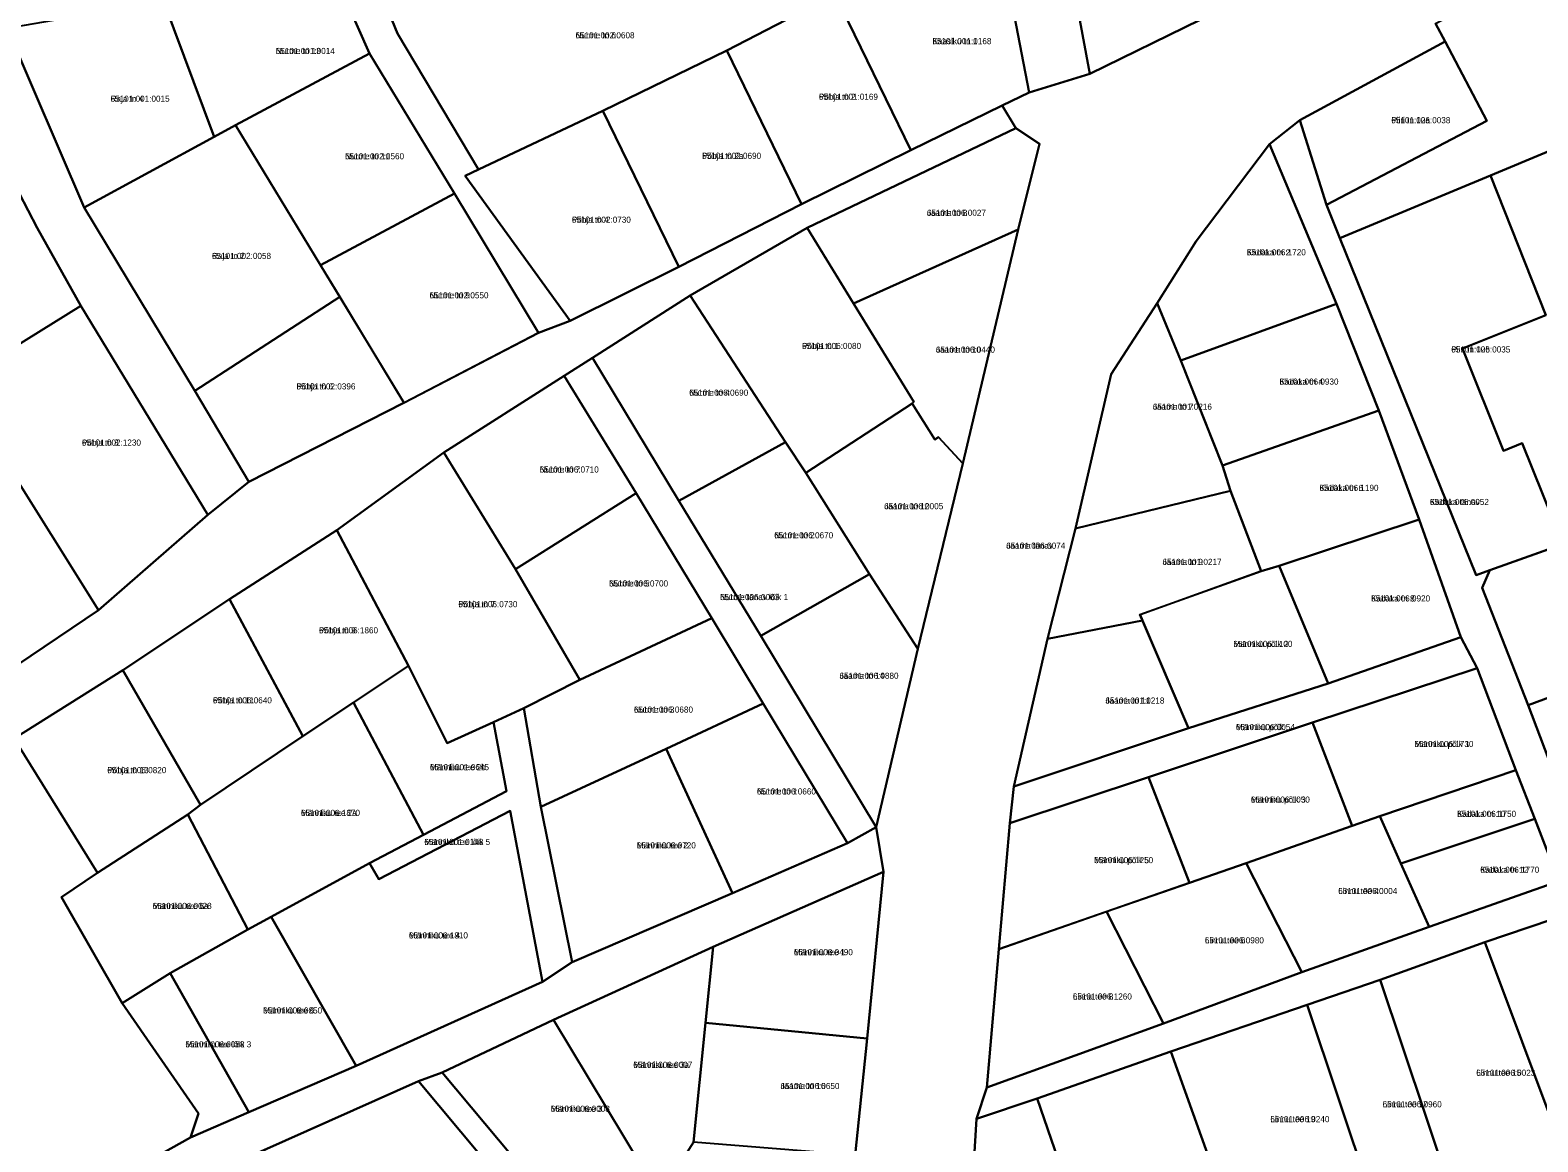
# Model space of a CAD drawing. Extents: x 556044 to 574504, y 6567077 to 6586269.
# Drawn here: x 560853.5 to 561223.9, y 6581367.4 to 6581640.5 of the extents above; entities that cross this region are included whole.
import ezdxf

# ---------------------------------------------------------------- set-up
doc = ezdxf.new("R2010")
doc.units = 0
for name, color, linetype in [('L_AADRESS', 7, 'Continuous'), ('PIIR', 7, 'Continuous'), ('TUNNUS', 7, 'Continuous')]:
    doc.layers.add(name, color=color, linetype=linetype)

msp = doc.modelspace()

# ---------------------------------------------------------------- linework, layer by layer
at = {"layer": 'PIIR'}
for points in [[(561073.04, 6582054.91), (561090.8, 6582052.25), (561063.5, 6581894.73), (561081.16, 6581800.3), (561086.75, 6581769.25), (561087.65, 6581765.33), (561095.83, 6581726.49), (561113.81, 6581629.73), (561098.93, 6581625.2), (561090.65, 6581668.07), (561080.32, 6581719.75), (561077.83, 6581733.6), (561073.27, 6581765.82), (561064.99, 6581804.94), (561063.2, 6581814.4), (561055.66, 6581860.95), (561050.77, 6581869.24), (561044.19, 6581869.12), (561046.86, 6581879.13), (561048.48, 6581913.41), (561048.56, 6581916.69), (561051.35, 6581917.01), (561064.29, 6581999.82)], [(560897.18, 6581521.41), (560865.96, 6581572.78), (560855.29, 6581591.94), (560850.86, 6581600.43), (560839.26, 6581625.44), (560835.81, 6581635.67), (560832.91, 6581651.09), (560829.15, 6581678.32), (560825.44, 6581705.91), (560821.71, 6581732.99), (560779.69, 6581727.72), (560778.17, 6581738.32), (560782.21, 6581739.06), (560790.39, 6581739.83), (560816.39, 6581742.34), (560828.68, 6581740.37), (560833.36, 6581733.14), (560834.71, 6581724.25), (560839.18, 6581696.6), (560843.5, 6581668.92), (560847.89, 6581640.98), (560866.8, 6581596.89), (560894, 6581551.88), (560907.3, 6581529.5)], [(561128.53, 6581730.52), (561140.95, 6581643.06), (561113.81, 6581629.73), (561095.83, 6581726.49)], [(560940.4, 6581647.93), (561002.17, 6581662.66), (561036.04, 6581670.75), (561041.6, 6581644.25), (561024.7, 6581635.46), (560994.21, 6581620.7), (560963.64, 6581606.24), (560943.81, 6581639.64)], [(561069.9, 6581611.01), (561051.43, 6581648.89), (561090.65, 6581668.07), (561098.93, 6581625.2), (561092.32, 6581621.96)], [(560898.72, 6581614.26), (560886.28, 6581647.65), (560928, 6581655.01), (560936.9, 6581634.78), (560904, 6581617.15)], [(561171.98, 6581597.55), (561211.35, 6581618.25), (561201.11, 6581637.72), (561198.78, 6581642.15), (561223.92, 6581655.37), (561234.5, 6581634.79), (561228.93, 6581632.93), (561231.61, 6581625.51), (561237.31, 6581628.21), (561241.95, 6581617.15), (561212.25, 6581604.8), (561175.27, 6581589.41)], [(560866.8, 6581596.89), (560847.89, 6581640.98), (560886.28, 6581647.65), (560898.72, 6581614.26)], [(561043, 6581597.71), (561024.7, 6581635.46), (561041.6, 6581644.25), (561051.43, 6581648.89), (561069.9, 6581611.01)], [(561165.4, 6581618.41), (561201.11, 6581637.72), (561211.35, 6581618.25), (561171.98, 6581597.55)], [(560957.8, 6581600.37), (560924.88, 6581582.76), (560904, 6581617.15), (560936.9, 6581634.78)], [(561012.85, 6581582.32), (560994.21, 6581620.7), (561024.7, 6581635.46), (561043, 6581597.71)], [(560986.22, 6581569.08), (560960.37, 6581604.69), (560963.64, 6581606.24), (560994.21, 6581620.7), (561012.85, 6581582.32)], [(561157.99, 6581612.48), (561165.4, 6581618.41), (561171.98, 6581597.55), (561175.27, 6581589.41), (561208.79, 6581506.62), (561212.14, 6581507.81), (561210.22, 6581503.5), (561221.52, 6581474.69), (561236.77, 6581434.42), (561229.03, 6581431.45), (561223.14, 6581446.77), (561218.48, 6581458.7), (561208.99, 6581483.75), (561204.95, 6581491.41), (561194.77, 6581520.27), (561184.86, 6581547.04), (561174.45, 6581573.3)], [(560894, 6581551.88), (560866.8, 6581596.89), (560898.72, 6581614.26), (560904, 6581617.15), (560924.88, 6581582.76), (560929.62, 6581574.95)], [(561044.41, 6581591.94), (561095.69, 6581616.41), (561101.45, 6581612.6), (561096.26, 6581591.49), (561055.81, 6581573.35)], [(561241.95, 6581617.15), (561277.97, 6581531.26), (561251.22, 6581521.73), (561230.01, 6581514.18), (561220.08, 6581539.06), (561215.46, 6581537.15), (561205.42, 6581562.26), (561225.85, 6581570.44), (561212.25, 6581604.8)], [(561130.36, 6581573.39), (561139.94, 6581588.63), (561157.99, 6581612.48), (561174.45, 6581573.3), (561136.21, 6581559.35)], [(561175.27, 6581589.41), (561212.25, 6581604.8), (561225.85, 6581570.44), (561205.42, 6581562.26), (561215.46, 6581537.15), (561220.08, 6581539.06), (561230.01, 6581514.18), (561212.14, 6581507.81), (561208.79, 6581506.62)], [(560850.86, 6581600.43), (560855.29, 6581591.94), (560865.96, 6581572.78), (560835.34, 6581553.74), (560825.53, 6581570.48), (560800.78, 6581556.15), (560796.99, 6581573.92)], [(560924.88, 6581582.76), (560957.8, 6581600.37), (560978.39, 6581566.14), (560945.42, 6581548.91)], [(561044.41, 6581591.94), (561070.65, 6581549.16), (561070.24, 6581548.78), (561044.05, 6581531.76), (561039.13, 6581539.31), (561015.68, 6581575.28)], [(561070.65, 6581549.16), (561055.81, 6581573.35), (561096.26, 6581591.49), (561082.63, 6581534.07), (561076.71, 6581540.54), (561075.78, 6581539.96), (561070.24, 6581548.78)], [(560894, 6581551.88), (560929.62, 6581574.95), (560945.37, 6581548.91), (560907.3, 6581529.5)], [(560991.72, 6581559.96), (561015.68, 6581575.28), (561039.13, 6581539.31), (561012.87, 6581524.89)], [(561119.12, 6581555.95), (561130.36, 6581573.39), (561136.31, 6581559.1), (561146.4, 6581533.52), (561148.37, 6581527.31), (561110.32, 6581518.06)], [(561146.4, 6581533.52), (561136.21, 6581559.35), (561174.45, 6581573.3), (561184.86, 6581547.04)], [(560825.53, 6581570.48), (560835.34, 6581553.74), (560870.37, 6581498.04), (560850.42, 6581484.58), (560800.78, 6581556.15)], [(560870.37, 6581498.04), (560835.34, 6581553.74), (560865.96, 6581572.78), (560897.18, 6581521.41)], [(560984.7, 6581555.6), (560991.72, 6581559.96), (561012.87, 6581524.89), (561033.07, 6581491.71), (561061.33, 6581444.69), (561054.34, 6581440.77), (561033.64, 6581475.11), (561021.02, 6581496.02), (561002.42, 6581526.74)], [(560955.14, 6581536.72), (560984.7, 6581555.6), (561002.42, 6581526.74), (560972.75, 6581508.04)], [(561059.75, 6581506.85), (561044.05, 6581531.76), (561070.24, 6581548.78), (561075.78, 6581539.96), (561076.71, 6581540.54), (561082.63, 6581534.07), (561071.64, 6581488.49)], [(561194.77, 6581520.27), (561160.38, 6581508.92), (561155.96, 6581507.57), (561148.37, 6581527.31), (561146.4, 6581533.52), (561184.86, 6581547.04)], [(560946.47, 6581484.35), (560928.85, 6581517.68), (560955.14, 6581536.72), (560972.75, 6581508.04), (560988.61, 6581480.89), (560974.78, 6581473.91), (560967.35, 6581470.52), (560955.94, 6581465.32)], [(561012.87, 6581524.89), (561039.13, 6581539.31), (561044.05, 6581531.76), (561059.75, 6581506.85), (561033.07, 6581491.71)], [(560972.75, 6581508.04), (561002.42, 6581526.74), (561021.02, 6581496.02), (560988.61, 6581480.89)], [(561103.45, 6581490.93), (561110.32, 6581518.06), (561148.37, 6581527.31), (561155.96, 6581507.57), (561126.21, 6581496.85), (561126.81, 6581495.45)], [(561210.22, 6581503.5), (561212.14, 6581507.81), (561251.22, 6581521.73), (561256.55, 6581506.8), (561242.42, 6581501.77), (561247.93, 6581484.38), (561221.52, 6581474.69)], [(560920.52, 6581467.09), (560902.54, 6581500.69), (560928.85, 6581517.68), (560946.47, 6581484.35), (560932.94, 6581475.36)], [(561172.4, 6581480.01), (561160.38, 6581508.92), (561194.77, 6581520.27), (561204.95, 6581491.41)], [(561061.33, 6581444.69), (561033.07, 6581491.71), (561059.75, 6581506.85), (561071.64, 6581488.49)], [(561138.07, 6581469.02), (561126.17, 6581496.95), (561155.96, 6581507.57), (561160.38, 6581508.92), (561172.4, 6581480.01)], [(560876.32, 6581483.3), (560902.54, 6581500.69), (560920.52, 6581467.09), (560895.35, 6581450.22)], [(560974.78, 6581473.91), (560988.61, 6581480.89), (561021.02, 6581496.02), (561033.64, 6581475.11), (561009.79, 6581463.95), (560979.02, 6581449.65)], [(561095.2, 6581454.65), (561103.45, 6581490.93), (561126.81, 6581495.45), (561138.07, 6581469.02)], [(561095.2, 6581454.65), (561138.07, 6581469.02), (561172.4, 6581480.01), (561204.95, 6581491.41), (561208.99, 6581483.75), (561168.53, 6581470.42), (561128.25, 6581456.94), (561094.19, 6581445.64)], [(560946.47, 6581484.35), (560955.94, 6581465.32), (560967.35, 6581470.52), (560970.56, 6581453.55), (560950.13, 6581442.79), (560932.94, 6581475.36)], [(561221.52, 6581474.69), (561247.93, 6581484.38), (561262.3, 6581443.26), (561236.77, 6581434.42)], [(560849.63, 6581466.49), (560876.32, 6581483.3), (560895.35, 6581450.22), (560892.29, 6581447.77), (560870.05, 6581433.46)], [(561168.53, 6581470.42), (561208.99, 6581483.75), (561218.48, 6581458.7), (561185.09, 6581447.41), (561178.33, 6581445.01)], [(560932.94, 6581475.36), (560950.13, 6581442.79), (560936.93, 6581435.84), (560912.72, 6581422.69), (560906.99, 6581419.57), (560892.29, 6581447.77), (560895.35, 6581450.22), (560920.52, 6581467.09)], [(560939.16, 6581431.95), (560936.93, 6581435.84), (560950.13, 6581442.79), (560970.56, 6581453.55), (560967.35, 6581470.52), (560974.78, 6581473.91), (560979.02, 6581449.65), (560986.67, 6581411.52), (560979.42, 6581406.72), (560971.48, 6581448.68)], [(561054.34, 6581440.77), (561026.11, 6581428.47), (561009.79, 6581463.95), (561033.64, 6581475.11)], [(560773.9, 6581423.09), (560847.24, 6581470.37), (560849.63, 6581466.49), (560870.05, 6581433.46), (560861.24, 6581427.52), (560876.14, 6581401.42), (560894.86, 6581374.38), (560892.91, 6581368.46), (560827.74, 6581332.04), (560800.22, 6581378.97)], [(561178.33, 6581445.01), (561152.26, 6581435.84), (561138.35, 6581431.02), (561128.25, 6581456.94), (561168.53, 6581470.42)], [(560979.02, 6581449.65), (561009.79, 6581463.95), (561026.11, 6581428.47), (560986.67, 6581411.52)], [(561223.14, 6581446.77), (561190.24, 6581435.74), (561185.09, 6581447.41), (561218.48, 6581458.7)], [(561094.19, 6581445.64), (561128.25, 6581456.94), (561138.35, 6581431.02), (561091.52, 6581414.76)], [(560870.05, 6581433.46), (560892.29, 6581447.77), (560906.99, 6581419.57), (560887.94, 6581408.86), (560876.14, 6581401.42), (560861.24, 6581427.52)], [(560936.93, 6581435.84), (560939.16, 6581431.95), (560971.48, 6581448.68), (560979.42, 6581406.72), (560933.6, 6581386.02), (560912.72, 6581422.69)], [(561152.26, 6581435.84), (561178.33, 6581445.01), (561185.09, 6581447.41), (561190.24, 6581435.74), (561197.21, 6581420.19), (561165.9, 6581409.11)], [(561229.03, 6581431.45), (561197.21, 6581420.19), (561190.24, 6581435.74), (561223.14, 6581446.77)], [(561059.19, 6581392.76), (561019.46, 6581396.6), (561021.3, 6581415.28), (561063.17, 6581433.71)], [(561117.97, 6581423.94), (561138.35, 6581431.02), (561152.26, 6581435.84), (561165.9, 6581409.11), (561131.91, 6581396.47)], [(560887.94, 6581408.86), (560906.99, 6581419.57), (560912.72, 6581422.69), (560933.6, 6581386.02), (560907.23, 6581374.7)], [(561088.57, 6581380.76), (561091.52, 6581414.76), (561117.97, 6581423.94), (561131.91, 6581396.47)], [(561232.68, 6581423.83), (561250.78, 6581374.98), (561231.11, 6581368.11), (561229.26, 6581367.46), (561210.87, 6581416.48)], [(561021.3, 6581415.28), (561019.46, 6581396.6), (561016.51, 6581367.31), (561008.13, 6581354.12), (560982.09, 6581397.36)], [(561210.87, 6581416.48), (561229.26, 6581367.46), (561232.35, 6581359.79), (561204.33, 6581349.93), (561202.03, 6581356.84), (561185.2, 6581407.17)], [(560876.14, 6581401.42), (560887.94, 6581408.86), (560907.23, 6581374.7), (560892.91, 6581368.46), (560894.86, 6581374.38)], [(561185.2, 6581407.17), (561202.03, 6581356.84), (561204.33, 6581349.93), (561186.63, 6581343.99), (561182.64, 6581355), (561167.24, 6581401.05)], [(561167.24, 6581401.05), (561182.64, 6581355), (561150.19, 6581343.67), (561133.76, 6581389.56)], [(560982.09, 6581397.36), (561008.13, 6581354.12), (560990.06, 6581348.08), (560986.17, 6581346.8), (560954.75, 6581384.44)], [(561056.18, 6581364.1), (561016.51, 6581367.31), (561019.46, 6581396.6), (561059.19, 6581392.76)], [(561100.94, 6581378.06), (561133.76, 6581389.56), (561150.19, 6581343.67), (561138.46, 6581339.69), (561112.96, 6581343.09)], [(560954.75, 6581384.44), (560986.17, 6581346.8), (560990.06, 6581348.08), (560999.33, 6581341.63), (561001.88, 6581338.76), (561012.18, 6581327.69), (561005.72, 6581322.81), (560985.29, 6581342.33), (560983.58, 6581340.88), (560964.33, 6581363.89), (560948.94, 6581382.29)], [(560910.91, 6581365.37), (560948.94, 6581382.29), (560964.33, 6581363.89), (560933.64, 6581338.23), (560926.38, 6581346.92)], [(561100.94, 6581378.06), (561112.96, 6581343.09), (561084.47, 6581347.13), (561086.01, 6581373.05)]]:
    msp.add_lwpolyline(points, close=True, dxfattribs=at)
for points in [[(560940.4, 6581647.93), (560943.81, 6581639.64), (560963.64, 6581606.24), (560960.37, 6581604.69), (560986.22, 6581569.08), (560978.39, 6581566.14), (560957.8, 6581600.37), (560936.9, 6581634.78), (560928, 6581655.01)], [(561056.18, 6581364.1), (561059.19, 6581392.76), (561063.17, 6581433.71), (561061.33, 6581444.69), (561071.64, 6581488.49), (561082.63, 6581534.07), (561096.26, 6581591.49), (561101.45, 6581612.6), (561095.69, 6581616.41), (561092.32, 6581621.96), (561098.93, 6581625.2), (561113.81, 6581629.73), (561140.95, 6581643.06)], [(561198.78, 6581642.15), (561201.11, 6581637.72), (561165.4, 6581618.41), (561157.99, 6581612.48), (561139.94, 6581588.63), (561130.36, 6581573.39), (561119.12, 6581555.95), (561110.32, 6581518.06), (561103.45, 6581490.93), (561095.2, 6581454.65), (561094.19, 6581445.64), (561091.52, 6581414.76), (561088.57, 6581380.76), (561086.01, 6581373.05), (561084.47, 6581347.13)], [(560850.42, 6581484.58), (560870.37, 6581498.04), (560897.18, 6581521.41), (560907.3, 6581529.5), (560945.37, 6581548.91), (560978.39, 6581566.14), (560986.22, 6581569.08), (561012.85, 6581582.32), (561043, 6581597.71), (561069.9, 6581611.01), (561092.32, 6581621.96), (561095.69, 6581616.41), (561044.41, 6581591.94), (561015.68, 6581575.28), (560991.72, 6581559.96), (560984.7, 6581555.6), (560955.14, 6581536.72), (560928.85, 6581517.68), (560902.54, 6581500.69), (560876.32, 6581483.3), (560849.63, 6581466.49)], [(560827.74, 6581332.04), (560892.91, 6581368.46), (560907.23, 6581374.7), (560933.6, 6581386.02), (560979.42, 6581406.72), (560986.67, 6581411.52), (561026.11, 6581428.47), (561054.34, 6581440.77), (561061.33, 6581444.69), (561063.17, 6581433.71), (561021.3, 6581415.28), (560982.09, 6581397.36), (560954.75, 6581384.44), (560948.94, 6581382.29), (560910.91, 6581365.37), (560900.02, 6581360.61), (560870.36, 6581344.66), (560863.64, 6581341.17), (560827.71, 6581321.69)], [(561232.68, 6581423.83), (561210.87, 6581416.48), (561185.2, 6581407.17), (561167.24, 6581401.05), (561133.76, 6581389.56), (561100.94, 6581378.06), (561086.01, 6581373.05), (561088.57, 6581380.76), (561131.91, 6581396.47), (561165.9, 6581409.11), (561197.21, 6581420.19), (561229.03, 6581431.45)]]:
    msp.add_lwpolyline(points, dxfattribs=at)

# ---------------------------------------------------------------- texts
at = {"layer": 'L_AADRESS'}
for s, p in [('Nurme tn 6', (560987.51, 6581638.49)), ('Nurme tn 13', (560913.88, 6581634.64)), ('Kaasiku tn 1', (561075.18, 6581637.05)), ('Raja tn 4', (560873.3, 6581622.91)), ('Põhja tn 2', (561047.3, 6581623.39)), ('Piiri tn 12a', (561187.91, 6581617.63)), ('Nurme tn 11', (560930.9, 6581608.77)), ('Põhja tn 2a', (561018.61, 6581608.88)), ('Jaama tn 8', (561073.83, 6581594.88)), ('Põhja tn 4', (560986.61, 6581593.19)), ('Raja tn 2', (560898.21, 6581584.29)), ('Kadaka tn 2', (561152.41, 6581585.18)), ('Nurme tn 9', (560951.64, 6581574.62)), ('Põhja tn 1', (561043.16, 6581562.17)), ('Jaama tn 10', (561076.04, 6581561.27)), ('Piiri tn 12b', (561202.64, 6581561.31)), ('Kadaka tn 4', (561160.44, 6581553.41)), ('Põhja tn 6', (560918.95, 6581552.23)), ('Nurme tn 4', (561015.43, 6581550.7)), ('Jaama tn 7', (561129.34, 6581547.25)), ('Põhja tn 8', (560866.26, 6581538.43)), ('Nurme tn 7', (560978.72, 6581531.82)), ('Kadaka tn 6', (561170.27, 6581527.3)), ('Kadaka tänav', (561197.38, 6581523.84)), ('Jaama tn 12', (561063.34, 6581522.8)), ('Nurme tn 2', (561036.31, 6581515.66)), ('Jaama tänav', (561093.32, 6581513.11)), ('Jaama tn 9', (561131.71, 6581509.12)), ('Nurme tn 5', (560995.76, 6581503.82)), ('Põhja tn 7', (560958.73, 6581498.73)), ('Nurme tänav lõik 1', (561023.02, 6581500.47)), ('Kadaka tn 8', (561182.95, 6581500.14)), ('Põhja tn 9', (560924.5, 6581492.31)), ('Männiku põik 2', (561149.12, 6581488.97)), ('Jaama tn 14', (561052.36, 6581481.14)), ('Põhja tn 11', (560898.42, 6581475.12)), ('Nurme tn 3', (561001.87, 6581472.83)), ('Jaama tn 11', (561117.67, 6581475.05)), ('Männiku põik', (561149.73, 6581468.53)), ('Männiku põik 1', (561193.59, 6581464.38)), ('Põhja tn 13', (560872.49, 6581457.96)), ('Männiku tee 2b', (560951.75, 6581458.69)), ('Nurme tn 1', (561032.07, 6581452.72)), ('Männiku põik 3', (561153.4, 6581450.72)), ('Männiku tee 2a', (560920.06, 6581447.46)), ('Kadaka tn 10', (561204.07, 6581447.22)), ('Männiku tee lõik 5', (560950.37, 6581440.32)), ('Männiku tee 2', (561002.57, 6581439.47)), ('Männiku põik 5', (561114.91, 6581435.85)), ('Kadaka tn 12', (561209.75, 6581433.48)), ('Linnu tee 4', (561174.86, 6581428.26)), ('Männiku tee 6a', (560883.64, 6581424.6)), ('Männiku tee 4', (560946.58, 6581417.35)), ('Linnu tee 6', (561142.11, 6581416.15)), ('Männiku tee 1', (561041.14, 6581413.24)), ('Linnu tee 8', (561109.68, 6581402.35)), ('Männiku tee 6', (560910.77, 6581398.92)), ('Männiku tee lõik 3', (560891.68, 6581390.6)), ('Männiku tee 3a', (561001.7, 6581385.56)), ('Linnu tee 15', (561208.78, 6581383.61)), ('Jaama tn 16', (561037.85, 6581380.35)), ('Linnu tee 17', (561185.79, 6581375.87)), ('Männiku tee 3', (560981.44, 6581374.76)), ('Linnu tee 19', (561158.2, 6581372.21))]:
    msp.add_text(s, height=1.5, dxfattribs=at).set_placement(p)
at = {"layer": 'TUNNUS'}
for s, p in [('65101:002:0608', (560987.51, 6581638.49)), ('65101:001:0014', (560913.88, 6581634.64)), ('65101:001:0168', (561075.18, 6581637.05)), ('65101:001:0015', (560873.3, 6581622.91)), ('65101:001:0169', (561047.3, 6581623.39)), ('65101:006:0038', (561187.91, 6581617.63)), ('65101:002:0560', (560930.9, 6581608.77)), ('65101:002:0690', (561018.61, 6581608.88)), ('65101:006:0027', (561073.83, 6581594.88)), ('65101:002:0730', (560986.61, 6581593.19)), ('65101:002:0058', (560898.21, 6581584.29)), ('65101:006:1720', (561152.41, 6581585.18)), ('65101:002:0550', (560951.64, 6581574.62)), ('65101:006:0080', (561043.16, 6581562.17)), ('65101:006:0440', (561076.04, 6581561.27)), ('65101:006:0035', (561202.64, 6581561.31)), ('65101:006:0930', (561160.44, 6581553.41)), ('65101:002:0396', (560918.95, 6581552.23)), ('65101:006:0690', (561015.43, 6581550.7)), ('65101:001:0216', (561129.34, 6581547.25)), ('65101:002:1230', (560866.26, 6581538.43)), ('65101:006:0710', (560978.72, 6581531.82)), ('65101:006:1190', (561170.27, 6581527.3)), ('65101:006:0052', (561197.38, 6581523.84)), ('65101:006:0005', (561063.34, 6581522.8)), ('65101:006:0670', (561036.31, 6581515.66)), ('65101:006:0074', (561093.32, 6581513.11)), ('65101:001:0217', (561131.71, 6581509.12)), ('65101:006:0700', (560995.76, 6581503.82)), ('65101:006:0730', (560958.73, 6581498.73)), ('65101:006:0063', (561023.02, 6581500.47)), ('65101:006:0920', (561182.95, 6581500.14)), ('65101:006:1860', (560924.5, 6581492.31)), ('65101:006:1100', (561149.12, 6581488.97)), ('65101:006:0880', (561052.36, 6581481.14)), ('65101:006:0640', (560898.42, 6581475.12)), ('65101:006:0680', (561001.87, 6581472.83)), ('65101:001:0218', (561117.67, 6581475.05)), ('65101:006:0054', (561149.73, 6581468.53)), ('65101:006:1730', (561193.59, 6581464.38)), ('65101:006:0820', (560872.49, 6581457.96)), ('65101:001:0645', (560951.75, 6581458.69)), ('65101:006:0660', (561032.07, 6581452.72)), ('65101:006:1050', (561153.4, 6581450.72)), ('65101:006:1870', (560920.06, 6581447.46)), ('65101:006:1750', (561204.07, 6581447.22)), ('65101:001:0148', (560950.37, 6581440.32)), ('65101:006:0720', (561002.57, 6581439.47)), ('65101:006:1250', (561114.91, 6581435.85)), ('65101:006:1770', (561209.75, 6581433.48)), ('65101:006:0004', (561174.86, 6581428.26)), ('65101:006:0028', (560883.64, 6581424.6)), ('65101:006:1810', (560946.58, 6581417.35)), ('65101:006:0980', (561142.11, 6581416.15)), ('65101:006:0490', (561041.14, 6581413.24)), ('65101:006:1260', (561109.68, 6581402.35)), ('65101:006:0850', (560910.77, 6581398.92)), ('65101:006:0088', (560891.68, 6581390.6)), ('65101:006:0007', (561001.7, 6581385.56)), ('65101:006:0023', (561208.78, 6581383.61)), ('65101:006:0650', (561037.85, 6581380.35)), ('65101:006:0960', (561185.79, 6581375.87)), ('65101:006:0008', (560981.44, 6581374.76)), ('65101:006:0240', (561158.2, 6581372.21))]:
    msp.add_text(s, height=1.5, dxfattribs=at).set_placement(p)

doc.saveas('drawing.dxf')
